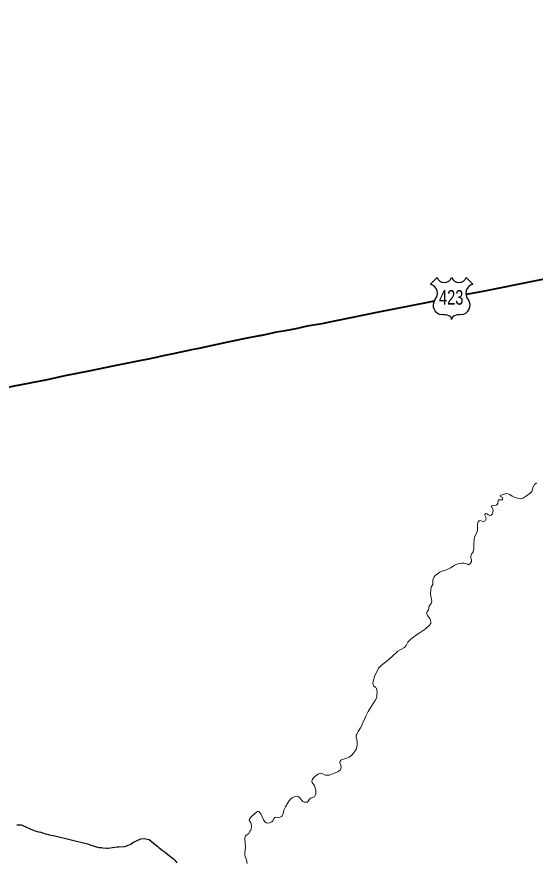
# Model space of a CAD drawing. Extents: x -1643653 to 4543381, y 1624270 to 13878484.
# Drawn here: x 587242 to 589726, y 8911844 to 8915895 of the extents above; entities that cross this region are included whole.
import ezdxf
from ezdxf.enums import TextEntityAlignment as Align

# ---------------------------------------------------------------- set-up
doc = ezdxf.new("R2010")
doc.units = 0
doc.header["$LTSCALE"] = 200
doc.layers.add('6', color=7, linetype='Continuous', lineweight=13)
doc.layers.add('60', color=7, linetype='Continuous', lineweight=13)

msp = doc.modelspace()

# ---------------------------------------------------------------- linework, layer by layer
at = {"layer": '6', "lineweight": 25}
for p, q in [((589223.6, 8914613.8), (589255.6, 8914645.8)), ((589395.4, 8914645.8), (589427.4, 8914613.8))]:
    msp.add_line(p, q, dxfattribs=at)
at = {"layer": '6', "lineweight": 40}
for points in [[(590967.2, 8914985.2), (590878.4, 8914955.6), (590794.3, 8914928.8), (590714.1, 8914902.8), (590638.7, 8914877.7), (590563.6, 8914852.3), (590490.5, 8914828.4), (590417.3, 8914804.2), (590344.2, 8914780.3), (590271, 8914756.5), (590202.2, 8914734.8), (590164.9, 8914722.1), (590133.8, 8914713.2), (590073.3, 8914697.5), (590013.2, 8914685.6), (589955.9, 8914674.1), (589907.1, 8914664.4), (589864, 8914655.5), (589824, 8914648.4), (589785.5, 8914641.2), (589761.6, 8914635.9), (589721.8, 8914628.2)], [(589721.8, 8914628.2), (589642.1, 8914611.9), (589562.3, 8914595.5), (589483.2, 8914580.8), (589404.8, 8914565.2), (589393.5, 8914562.8)], [(589240.3, 8914531.9), (589219.4, 8914527.9), (588967.4, 8914478), (588717.5, 8914427.5), (588703.5, 8914423.5), (588633.7, 8914412.4), (588579.1, 8914399.7), (588527.3, 8914390), (588477.7, 8914381.7), (588437.3, 8914372.2), (588399.5, 8914364.9)], [(588411.7, 8914367.2), (588329.2, 8914351.8), (588253.3, 8914335.7), (588178.5, 8914319.1), (588105.9, 8914304.4), (588087.3, 8914299.9)], [(588087.3, 8914299.9), (587991.2, 8914280), (587942.9, 8914269.9)], [(587942.9, 8914269.9), (587894.7, 8914259.8), (587797.8, 8914239.6), (587700.8, 8914220), (587586.4, 8914197.2), (587471.4, 8914174.2), (587387.3, 8914155.4), (587304, 8914139.1), (587220.7, 8914122.7), (587137.7, 8914106.3), (587056.1, 8914089), (587006.5, 8914079.3)]]:
    msp.add_lwpolyline(points, dxfattribs=at)
at = {"layer": '6'}
for points in [[(589732.6, 8913661.8), (589723.6, 8913652.9), (589717.2, 8913642.7), (589709.6, 8913620.5), (589705.8, 8913614.7), (589702.7, 8913611.7), (589683.9, 8913599.8), (589669.4, 8913589.6), (589663.5, 8913586.8), (589656.5, 8913585.3), (589652.4, 8913585.5), (589625.6, 8913592.9), (589615.1, 8913598.1), (589604.5, 8913605.5), (589594.8, 8913609.3), (589588.7, 8913609.9), (589581.5, 8913609.2), (589568.2, 8913604.4), (589561.1, 8913602.8), (589558.6, 8913600.4), (589559.1, 8913598), (589560.4, 8913596.6), (589570, 8913590.6), (589571, 8913585.4), (589570.1, 8913582.2), (589568.5, 8913580.6), (589566.4, 8913580), (589554.3, 8913580.6), (589550.8, 8913579.8), (589548.3, 8913575.2), (589546.7, 8913562.5), (589543.5, 8913558.1), (589538.4, 8913554.9), (589524.5, 8913552.9), (589519, 8913550.7), (589517.5, 8913549.1), (589517.5, 8913546.1), (589523, 8913535.2), (589524, 8913529), (589523.7, 8913520.8), (589520.5, 8913511.4), (589515.2, 8913507.2), (589508.7, 8913505.4), (589501.8, 8913507.6), (589493.6, 8913513.4), (589489.8, 8913513.8), (589486.5, 8913512.9), (589485.4, 8913511.3), (589485.5, 8913507.3), (589489.8, 8913497.1), (589490.8, 8913490.3), (589490, 8913486.3), (589486.4, 8913479.7), (589482.6, 8913477.5), (589477, 8913476.1), (589467.2, 8913479.9), (589460.9, 8913481.3), (589457.6, 8913479.4), (589453.3, 8913475), (589450.1, 8913463.6), (589449.3, 8913437.6), (589447.7, 8913427.2), (589437.8, 8913409.9)], [(589437.8, 8913409.9), (589433.1, 8913393.5), (589433.1, 8913393.5), (589431.5, 8913367.8), (589432.1, 8913345.4), (589431.2, 8913338.2), (589428.5, 8913331.2), (589421, 8913319.9), (589417.5, 8913311.9), (589417.5, 8913302.5), (589420.9, 8913290.9), (589420.9, 8913284.3), (589416.4, 8913276.5), (589406.9, 8913269), (589396.3, 8913273)], [(589396.3, 8913273), (589390.8, 8913274.8), (589383.3, 8913276), (589373.9, 8913276), (589361.7, 8913275), (589346.8, 8913270.5), (589338, 8913265.9), (589320.9, 8913254.3), (589310.8, 8913248.6), (589298.3, 8913243.4), (589287.1, 8913241.2), (589280.3, 8913239), (589268.3, 8913232.8), (589257.4, 8913225.7), (589246.9, 8913216.7), (589242.3, 8913210.5), (589235.2, 8913196), (589234.8, 8913187.8)], [(589234.8, 8913187.8), (589236.1, 8913183.2), (589235.3, 8913175), (589229.7, 8913165.4), (589227.3, 8913159.4), (589224.2, 8913136.7), (589224.2, 8913129.5), (589225.4, 8913118.3), (589229.5, 8913102.9), (589230.1, 8913092.7), (589227.2, 8913082.8), (589221.5, 8913075.8), (589218.6, 8913070), (589215.3, 8913053.2), (589208.5, 8913045), (589207.2, 8913041.9), (589206.6, 8913037.8), (589207.5, 8913031.5), (589209.8, 8913025.7), (589220.4, 8913011.7), (589224.2, 8913003.7), (589226.6, 8912994.5), (589225.1, 8912987.7)], [(589225.1, 8912987.7), (589225.1, 8912987.7), (589217.9, 8912977.7), (589198, 8912959.6), (589184.3, 8912950.4), (589169.3, 8912941.7), (589151.8, 8912930.3), (589128.6, 8912911.4), (589116.4, 8912898.2), (589106.9, 8912881.9), (589099, 8912871.9), (589068.3, 8912854), (589062.8, 8912850), (589025, 8912815.3), (588987.8, 8912786.4), (588979.9, 8912778.8), (588975.2, 8912772.6), (588963.1, 8912750.1), (588957.9, 8912738.7), (588949.9, 8912709.8), (588948, 8912700.2), (588950.1, 8912694.8), (588951.6, 8912688.4), (588953.3, 8912687.2), (588960.2, 8912683), (588963, 8912678.7), (588965.1, 8912677), (588967.8, 8912668.8), (588968.2, 8912654.7), (588967.7, 8912650.4), (588967.8, 8912636.2), (588962.2, 8912622.8), (588956.7, 8912616.2), (588925.6, 8912566.2), (588921.1, 8912556.2), (588914.4, 8912544), (588910, 8912532.8), (588904.4, 8912520.6), (588896.9, 8912507.2), (588894.7, 8912498.6), (588888.9, 8912486.8), (588877.2, 8912470.3), (588870.5, 8912457.5), (588868.6, 8912451.7), (588868.1, 8912445.7), (588872, 8912422.7), (588872.3, 8912407.2), (588870.6, 8912394.4), (588867.9, 8912385), (588863.4, 8912376.8), (588854, 8912364.7), (588846.6, 8912357.1), (588834.5, 8912347.5), (588826.4, 8912343.3), (588798.1, 8912333.4), (588795.1, 8912331.6), (588791.9, 8912328), (588789.9, 8912324), (588789.2, 8912319.6), (588794.8, 8912308), (588795.9, 8912300.3), (588794.5, 8912291.7), (588790.7, 8912285.1), (588778.4, 8912277.1), (588756.6, 8912266.8)], [(588756.6, 8912266.8), (588738.9, 8912261), (588729, 8912260.2), (588721.3, 8912260.6), (588715.5, 8912262.2), (588704.7, 8912268.2), (588696.6, 8912269.5), (588685.5, 8912265.7), (588677.7, 8912261.1), (588667.4, 8912252.3), (588662.1, 8912246.2), (588656.9, 8912238.2), (588655.1, 8912231.8), (588655.1, 8912228.4), (588656.5, 8912225), (588667.9, 8912208.6), (588674.8, 8912188.2), (588675.3, 8912182.2), (588674.1, 8912170.3), (588671.1, 8912162.7), (588667.4, 8912157.3), (588664.2, 8912155.3), (588654.1, 8912152.3), (588649.2, 8912149.7), (588644.3, 8912144.9), (588637.8, 8912135.8), (588632.8, 8912131.8), (588624.2, 8912130.4), (588618.8, 8912131), (588612, 8912134), (588607, 8912139.8), (588597.9, 8912152.2), (588589.9, 8912158.2), (588585, 8912159.2), (588577.3, 8912158.2), (588568.1, 8912155.6), (588561.2, 8912152.3)], [(588561.2, 8912152.3), (588555.2, 8912147.5), (588555.2, 8912147.5), (588545.5, 8912135.7), (588539.6, 8912127.1), (588528.7, 8912108.2), (588522.9, 8912095.4), (588516.2, 8912072.3), (588513.1, 8912065.3), (588509.3, 8912061.9), (588503.8, 8912058.9), (588497.4, 8912058.3), (588483, 8912058.5), (588478.7, 8912057.3), (588473.2, 8912052.1), (588467.8, 8912041), (588463.6, 8912036.6), (588452.4, 8912032), (588443.2, 8912030.8), (588437.8, 8912032.2), (588429.9, 8912036.8), (588423.7, 8912046), (588410.3, 8912075.8), (588403.6, 8912084.6), (588400.1, 8912086.8), (588394.6, 8912086), (588390.3, 8912083.4), (588365.5, 8912061.7), (588359.5, 8912054.9), (588356.7, 8912049.9), (588355.7, 8912044.4), (588362.5, 8912031.8), (588364.3, 8912026.8), (588365.7, 8912012.2), (588364.9, 8912002.8), (588362.5, 8911996.8), (588358.7, 8911991.4), (588353.5, 8911981.3), (588348.9, 8911977.1), (588343.1, 8911975.1), (588337.9, 8911970.1), (588335.9, 8911965.3), (588334.5, 8911956.3), (588336.7, 8911916), (588336.1, 8911901.6), (588334.4, 8911890.4), (588333.8, 8911879.4), (588335.3, 8911869.1), (588341.8, 8911854.7), (588344.9, 8911837.5)]]:
    msp.add_lwpolyline(points, dxfattribs=at)
at = {"layer": '6', "lineweight": 25}
for points in [[(587242, 8912022.3), (587254.1, 8912022.7), (587261.3, 8912021.9), (587267.1, 8912020.3), (587272.7, 8912018.3), (587284.8, 8912013.3), (587309, 8912000.9), (587320.6, 8911996.1), (587327.4, 8911993.9), (587344.5, 8911989.4), (587356.6, 8911986.8), (587368.5, 8911983), (587385.5, 8911978.2), (587392.4, 8911976.6), (587398.4, 8911974.8), (587404.2, 8911973.2), (587422.6, 8911970.3), (587579.2, 8911930.7)], [(587579.2, 8911930.7), (587589.2, 8911927.7), (587596.7, 8911925.5), (587628.1, 8911915.7)], [(587628.1, 8911915.7), (587634.9, 8911914.1), (587641.3, 8911913.1), (587647.7, 8911913.1), (587653.9, 8911912.7), (587673.1, 8911910.6), (587679.5, 8911910.6), (587700.5, 8911913.8), (587722.3, 8911916.2), (587729.5, 8911917.3), (587758.9, 8911918.9), (587780.4, 8911926.8), (587787.2, 8911930.2), (587797.3, 8911937.2), (587835.2, 8911955.7), (587851.9, 8911957.5), (587875.4, 8911952.9), (587904.7, 8911928.2), (587917.4, 8911917.8), (587924, 8911911.8), (587937.7, 8911901.4), (587952.1, 8911891), (587965.4, 8911880), (587986, 8911864), (587992.3, 8911858.8), (587998.1, 8911853), (588003.8, 8911846.6), (588008.1, 8911839.6)]]:
    msp.add_lwpolyline(points, dxfattribs=at)
for centre, radius, start, end in [((589290.5, 8914659.2), 37.4, 200.9593, 339.0407), ((589360.5, 8914659.2), 37.4, 200.9593, 339.0407), ((589211.2, 8914569.5), 46.1, 317.5721, 74.3689), ((589439.8, 8914569.5), 46.1, 105.6277, 222.4279), ((589281.9, 8914512.4), 44.9, 144.7373, 264.6578), ((589369.1, 8914512.4), 44.9, 275.3422, 35.2627), ((589277.5, 8914349.7), 118, 72.8937, 89.9006), ((589306.6, 8914444.4), 18.9, 357.6934, 72.9296), ((589344.4, 8914444.4), 18.9, 107.0704, 182.3065), ((589373.5, 8914349.7), 118, 90.0994, 107.1063)]:
    msp.add_arc(centre, radius, start, end, dxfattribs=at)
at = {"layer": '60', "lineweight": 25}
msp.add_spline([(814781, 9009175.5), (814787.2, 9009173.4), (814796.9, 9009173.4), (814799.4, 9009172.4), (814805.1, 9009174.5), (814805.6, 9009176.5), (814811.7, 9009179.5), (814811.7, 9009179.5), (814801.5, 9009181), (814790.7, 9009181.5), (814784.1, 9009183.1), (814777.4, 9009185.1), (814778.4, 9009175.5)], degree=3, dxfattribs=at)

# ---------------------------------------------------------------- texts
at = {"layer": '6', "width": 0.75}
msp.add_text('423', height=70, dxfattribs=at).set_placement((589323.4, 8914515.5), align=Align.CENTER)

doc.saveas('drawing.dxf')
